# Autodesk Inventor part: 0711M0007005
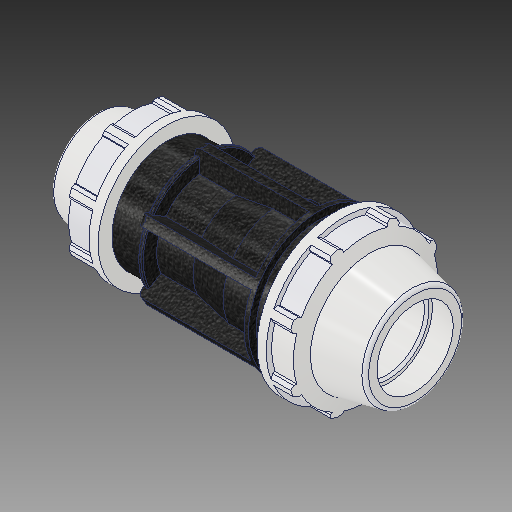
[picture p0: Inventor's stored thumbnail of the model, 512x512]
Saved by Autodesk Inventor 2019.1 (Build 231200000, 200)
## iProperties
Created: 2017-02
Part Number: 0711M0007005
Material: PVC-Piping
Description: PLASSON REDUCING COUPLER 3/4'' - 1/2''
Document SubType Name: Modeling
Designer: KIM
Mass: 92.6774 g
Surface Area: 199.44 cm^2
Volume: 66.1981 cm^3
Density: 1.4 g/cm^3
Appearance: PTFE
Author: KIM
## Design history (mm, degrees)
derived "0711M0.ipt"
feature "Solid1::0711M0.ipt"
tag "TaggingFeature1"
body "Solid1"
other parameters: "d2" = 26.6, "d4" = 9.25, "d5" = 15.85714, "d7" = 54.102, "d9" = 15.85714, "d11" = 1.58571, "d12" = 43.2816, "d13" = 120 deg, "d14" = 34.58, "d15" = 12 deg, "d16" = 48.6918, "d18" = 1.33, "d19" = 35 deg, "d20" = 17.5 deg, "d21" = 50.31486, "d23" = 0, "d25" = 360 deg, "d27" = 1.08204, "d42" = 12.21, "d46" = 0.798, "d51" = 111, "d52" = 38.27586, "d53" = 12 deg, "d54" = 48.006, "d56" = 31.8, "d57" = 21.2, "d58" = 23.94, "d59" = 19.08, "d60" = 43.2054, "d61" = 38.4048, "d62" = 11.1, "d63" = 13.32, "d64" = 120 deg, "d65" = 48.006, "d68" = 7.92857, "d74" = 44.64558, "d75" = 35 deg, "d76" = 17.5 deg, "d78" = 0, "d80" = 360 deg, "d85" = 0.96012, "d88" = 0.424, "d94" = 37.8714, "d97" = 1.96857, "d98" = 3.2004, "d99" = 0, "d100" = 2.16408, "d102" = 360 deg, "d104" = 2, "d106" = 0, "d107" = 3.2004, "d108" = 0, "d109" = 3.2004, "d110" = 0, "d_" = 26.6, "E_" = 54.102, "H_" = 111, "l_" = 48.006, "d_1" = 21.2, "E_1" = 48.006, "d96" = 5.9057
